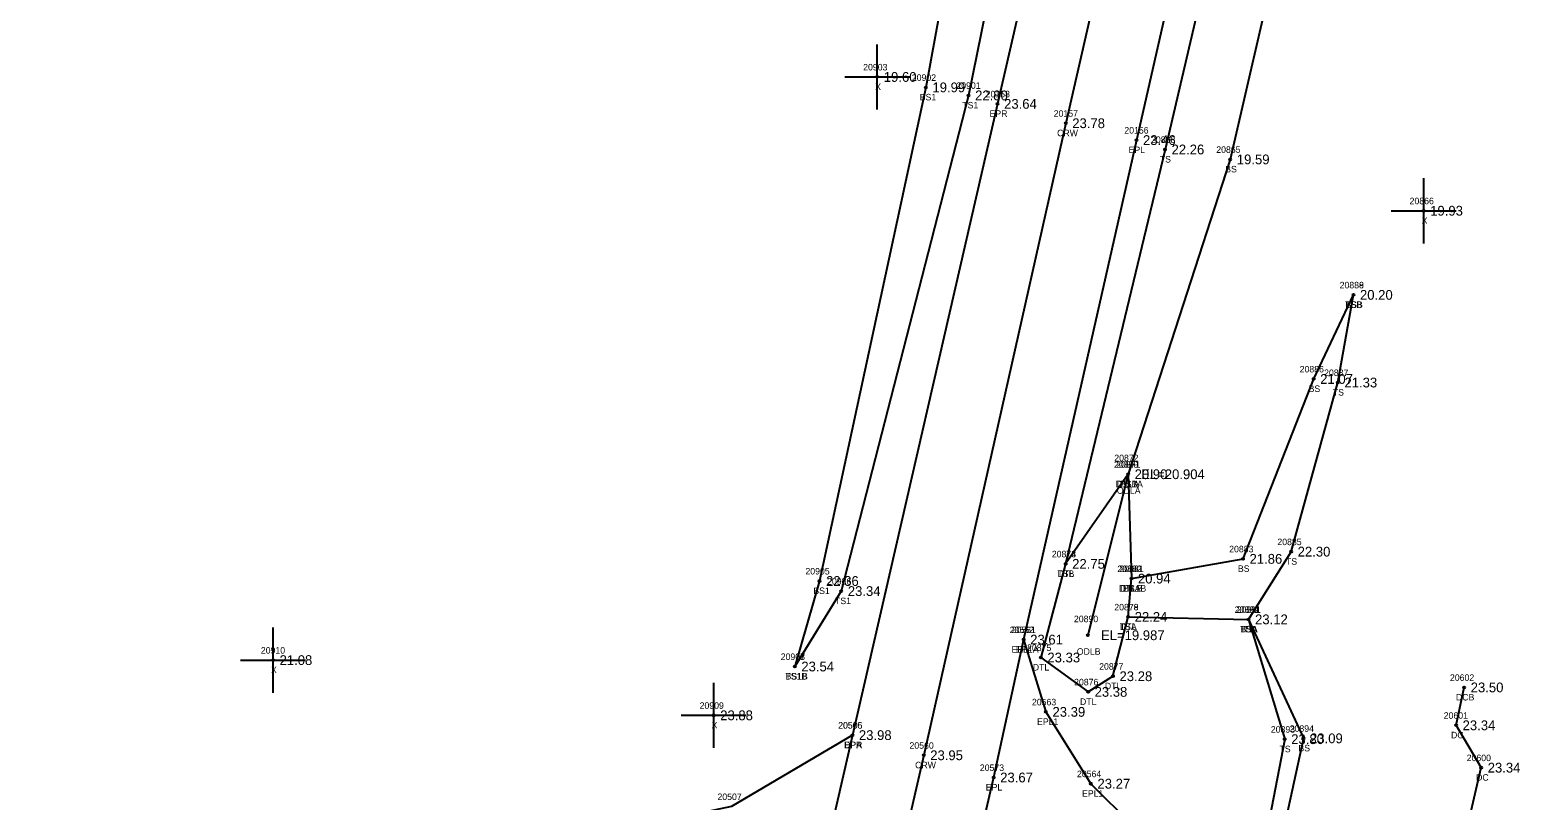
# Model space of a CAD drawing. Extents: x 2655177 to 2656219, y 761780 to 764748.
# Drawn here: x 2655478.9 to 2655710.1, y 762799.3 to 762917.5 of the extents above; entities that cross this region are included whole.
import ezdxf

# ---------------------------------------------------------------- set-up
doc = ezdxf.new("R2010")
doc.units = 0
for name, color, linetype in [('RD_DTM_BkLn1', 7, 'Continuous'), ('RD_DTM_BkLn2', 7, 'Continuous'), ('RD_DTM_BkLn_txCode', 7, 'Continuous'), ('RD_EX_Conc', 7, 'Continuous'), ('RD_EX_Conc_txCode', 7, 'Continuous'), ('RD_EX_Driveway', 7, 'Continuous'), ('RD_EX_Driveway_txCode', 7, 'Continuous'), ('RD_EX_H2O', 7, 'Continuous'), ('RD_EX_H2O_txCode', 7, 'Continuous'), ('RD_EX_Misc', 7, 'Continuous'), ('RD_EX_Misc_txCode', 7, 'Continuous'), ('RD_EX_Road', 7, 'Continuous'), ('RD_EX_Road_txCode', 7, 'Continuous'), ('RD_EX_TX_Conc_ELEV', 7, 'Continuous'), ('RD_EX_TX_Driveway_ELEV', 7, 'Continuous'), ('RD_EX_TX_H2O_ELEV', 7, 'Continuous'), ('RD_EX_TX_Misc_ELEV', 7, 'Continuous'), ('RD_EX_TX_Road_ELEV', 7, 'Continuous'), ('RD_HC_Survey_ELEV', 7, 'Continuous'), ('RD_HC_Survey_txCode', 7, 'Continuous'), ('RD_SMD_Locator', 7, 'Continuous')]:
    doc.layers.add(name, color=color, linetype=linetype)

msp = doc.modelspace()

# ---------------------------------------------------------------- linework, layer by layer
at = {"layer": 'RD_DTM_BkLn1'}
msp.add_lwpolyline([(2655711.06, 763230.3), (2655703.38, 763195.9), (2655681.97, 763099.65), (2655659.44, 762998.39), (2655637.72, 762903.26), (2655615.94, 762806.28), (2655593.94, 762710.45), (2655572.67, 762616.37), (2655551.12, 762519.58), (2655528.83, 762422.13), (2655507.58, 762326.81), (2655486.01, 762234.2), (2655464.77, 762141.12), (2655442.2, 762047.28), (2655420.99, 761952.95), (2655398.79, 761855.74), (2655384.11, 761791.21)], dxfattribs=at)
at = {"layer": 'RD_DTM_BkLn2'}
for points in [[(2655696.84, 763233.58), (2655686.81, 763240.78), (2655674.65, 763210.56), (2655653.92, 763107.89), (2655633.81, 763004.63), (2655616.28, 762908.76), (2655599.96, 762833.02), (2655596.17, 762819.9)], [(2655696.84, 763233.58), (2655686.68, 763198.57), (2655665.58, 763104.06), (2655642.01, 763002.21), (2655622.83, 762907.53), (2655603.3, 762831.47), (2655596.17, 762819.9)], [(2655744.66, 763205.12), (2655733.04, 763202.26), (2655726.56, 763191.09), (2655699.62, 763095.24), (2655675.04, 762993.86), (2655652.95, 762899.23), (2655637.71, 762835.65)], [(2655744.66, 763205.12), (2655742.37, 763185.6), (2655710.01, 763092), (2655684.24, 762990.11), (2655662.96, 762897.71), (2655647.29, 762849.4)], [(2655647.29, 762827.51), (2655665.76, 762827.13), (2655672.29, 762837.52), (2655679.47, 762863.47), (2655681.85, 762876.92)], [(2655647.79, 762833.39), (2655664.91, 762836.42), (2655675.75, 762864.02), (2655681.85, 762876.92)], [(2655665.76, 762827.13), (2655671.3, 762808.75), (2655668.39, 762793.68), (2655669.85, 762789.01)], [(2655665.76, 762827.13), (2655674.19, 762808.88), (2655670.96, 762794.12), (2655669.85, 762789.01)]]:
    msp.add_lwpolyline(points, dxfattribs=at)
at = {"layer": 'RD_EX_Conc'}
msp.add_lwpolyline([(2655695.58, 762778.92), (2655701.44, 762804.38), (2655697.59, 762810.88), (2655698.83, 762816.69)], dxfattribs=at)
at = {"layer": 'RD_EX_Driveway'}
msp.add_lwpolyline([(2655605, 762809.37), (2655586.47, 762798.41), (2655573.36, 762795.67), (2655559.24, 762787.47), (2655545.04, 762765.33), (2655541.01, 762760.72), (2655533.69, 762755.14), (2655505.04, 762752.17)], dxfattribs=at)
at = {"layer": 'RD_EX_H2O'}
for q in [(2655641.13, 762824.7), (2655647.79, 762833.39)]:
    msp.add_line((2655647.29, 762849.4), q, dxfattribs=at)
msp.add_lwpolyline([(2655647.29, 762849.4), (2655637.71, 762835.65), (2655633.91, 762821.28), (2655641.15, 762816.01), (2655644.97, 762818.41), (2655647.29, 762827.51), (2655647.79, 762833.39)], dxfattribs=at)
at = {"layer": 'RD_EX_Misc'}
for p, q in [((2655608.82, 762905.36), (2655608.82, 762915.36)), ((2655603.82, 762910.36), (2655613.82, 762910.36)), ((2655692.62, 762884.83), (2655692.62, 762894.83)), ((2655687.62, 762889.83), (2655697.62, 762889.83)), ((2655516.15, 762815.88), (2655516.15, 762825.88)), ((2655511.15, 762820.88), (2655521.15, 762820.88)), ((2655583.73, 762807.41), (2655583.73, 762817.41)), ((2655578.73, 762812.41), (2655588.73, 762812.41))]:
    msp.add_line(p, q, dxfattribs=at)
at = {"layer": 'RD_EX_Road'}
for points in [[(2655700.99, 763232.28), (2655693.55, 763198.57), (2655671.65, 763102.04), (2655649.04, 763001.06), (2655627.27, 762906.23), (2655605, 762809.37), (2655598.99, 762783.09), (2655583.65, 762714.14), (2655561.97, 762618.32), (2655556.36, 762593.84), (2655548.11, 762557.14), (2655540.1, 762522.48), (2655518.03, 762425.04), (2655496.48, 762329.56), (2655475.55, 762236.62), (2655473.2, 762226.14), (2655466.57, 762197.5), (2655460.06, 762168.16), (2655454.26, 762143.78), (2655432.5, 762049.88), (2655410.7, 761955.51), (2655388.17, 761858.43), (2655373.5, 761793.95)], [(2655722.66, 763227.87), (2655714.47, 763193.23), (2655692.89, 763097.26), (2655670.04, 762995.18), (2655648.57, 762900.67), (2655631.27, 762824.03), (2655626.67, 762802.87), (2655621.78, 762781.91), (2655611.71, 762738.43), (2655604.93, 762708.62), (2655582.64, 762610.54), (2655576.46, 762583.32), (2655561.41, 762517.24)], [(2655631.27, 762824.03), (2655634.69, 762812.94), (2655641.59, 762801.92), (2655647.95, 762795.55)]]:
    msp.add_lwpolyline(points, dxfattribs=at)
at = {"layer": 'RD_SMD_Locator'}
for centre in [(2655608.82, 762910.36), (2655616.28, 762908.76), (2655622.83, 762907.53), (2655627.27, 762906.23), (2655637.72, 762903.26), (2655648.57, 762900.67), (2655652.95, 762899.23), (2655662.96, 762897.71), (2655692.62, 762889.83), (2655681.85, 762876.92), (2655681.85, 762876.92), (2655675.75, 762864.02), (2655679.47, 762863.47), (2655647.29, 762849.4), (2655647.29, 762849.4), (2655647.29, 762849.4), (2655647.29, 762849.4), (2655672.29, 762837.52), (2655637.71, 762835.65), (2655637.71, 762835.65), (2655664.91, 762836.42), (2655599.96, 762833.02), (2655647.79, 762833.39), (2655647.79, 762833.39), (2655647.79, 762833.39), (2655603.3, 762831.47), (2655647.29, 762827.51), (2655647.29, 762827.51), (2655665.76, 762827.13), (2655665.76, 762827.13), (2655665.76, 762827.13), (2655631.27, 762824.03), (2655631.27, 762824.03), (2655641.13, 762824.7), (2655516.15, 762820.88), (2655633.91, 762821.28), (2655596.17, 762819.9), (2655596.17, 762819.9), (2655644.97, 762818.41), (2655698.83, 762816.69), (2655641.15, 762816.01), (2655583.73, 762812.41), (2655634.69, 762812.94), (2655605, 762809.37), (2655605, 762809.37), (2655697.59, 762810.88), (2655671.3, 762808.75), (2655674.19, 762808.88), (2655615.94, 762806.28), (2655626.67, 762802.87), (2655701.44, 762804.38), (2655641.59, 762801.92)]:
    msp.add_circle(centre, 0.15, dxfattribs=at)

# ---------------------------------------------------------------- texts
at = {"layer": 'RD_DTM_BkLn_txCode'}
for s, p in [('20902', (2655614.12, 762909.76)), ('20901', (2655620.95, 762908.53)), ('BS1', (2655615.33, 762906.76)), ('TS1', (2655621.86, 762905.53)), ('20868', (2655650.81, 762900.23)), ('20865', (2655660.81, 762898.71)), ('TS', (2655652.15, 762897.23)), ('BS', (2655662.18, 762895.71)), ('20888', (2655679.73, 762877.92)), ('20889', (2655679.73, 762877.92)), ('TSB', (2655680.58, 762874.92)), ('BSB', (2655680.6, 762874.92)), ('20886', (2655673.6, 762865.02)), ('20887', (2655677.35, 762864.47)), ('BS', (2655674.97, 762862.02)), ('TS', (2655678.68, 762861.47)), ('20869', (2655645.15, 762850.4)), ('BSB', (2655646.04, 762847.4)), ('20885', (2655670.18, 762838.52)), ('20873', (2655635.59, 762836.65)), ('20883', (2655662.79, 762837.42)), ('20905', (2655597.8, 762834.02)), ('20880', (2655645.63, 762834.39)), ('BS', (2655664.13, 762834.42)), ('TS', (2655671.5, 762835.52)), ('20906', (2655601.12, 762832.47)), ('TSB', (2655636.44, 762833.65)), ('BS1', (2655599.01, 762831.02)), ('TS1', (2655602.34, 762829.47)), ('BSA', (2655646.52, 762831.39)), ('20879', (2655645.17, 762828.51)), ('20884', (2655663.64, 762828.13)), ('20892', (2655663.64, 762828.13)), ('20891', (2655663.92, 762828.13)), ('TSA', (2655646.01, 762825.51)), ('TSA', (2655664.47, 762825.13)), ('BSA', (2655664.49, 762825.13)), ('TS', (2655664.96, 762825.13)), ('20907', (2655594.01, 762820.9)), ('20908', (2655594.01, 762820.9)), ('TS1B', (2655594.73, 762817.9)), ('BS1B', (2655594.75, 762817.9)), ('20893', (2655669.18, 762809.75)), ('20894', (2655672.07, 762809.88)), ('TS', (2655670.5, 762806.75)), ('BS', (2655673.41, 762806.88))]:
    msp.add_text(s, height=1, dxfattribs=at).set_placement(p)
at = {"layer": 'RD_EX_Conc_txCode'}
for s, p in [('20602', (2655696.65, 762817.69)), ('DCB', (2655697.57, 762814.69)), ('20601', (2655695.69, 762811.88)), ('DC', (2655696.81, 762808.88)), ('20600', (2655699.22, 762805.38)), ('DC', (2655700.66, 762802.38))]:
    msp.add_text(s, height=1, dxfattribs=at).set_placement(p)
at = {"layer": 'RD_EX_Driveway_txCode'}
for s, p in [('20506', (2655602.81, 762810.37)), ('DPA', (2655603.73, 762807.37)), ('20507', (2655584.31, 762799.41))]:
    msp.add_text(s, height=1, dxfattribs=at).set_placement(p)
at = {"layer": 'RD_EX_H2O_txCode'}
for s, p in [('20870', (2655645.13, 762850.4)), ('20872', (2655645.17, 762851.4)), ('20871', (2655645.45, 762850.4)), ('DTL1A', (2655645.39, 762847.4)), ('ODLA', (2655645.56, 762846.4)), ('DTLA', (2655645.56, 762847.4)), ('20874', (2655635.59, 762836.65)), ('20882', (2655645.67, 762834.39)), ('20881', (2655645.96, 762834.39)), ('DTL', (2655636.46, 762833.65)), ('DTL1B', (2655645.91, 762831.39)), ('DTLB', (2655646.08, 762831.39)), ('20878', (2655645.17, 762828.51)), ('20890', (2655638.98, 762826.7)), ('DTL', (2655646.05, 762825.51)), ('20875', (2655631.79, 762822.28)), ('ODLB', (2655639.42, 762821.7)), ('DTL', (2655632.67, 762819.28)), ('20877', (2655642.85, 762819.41)), ('20876', (2655639.01, 762817.01)), ('DTL', (2655643.72, 762816.41)), ('DTL', (2655639.91, 762814.01))]:
    msp.add_text(s, height=1, dxfattribs=at).set_placement(p)
at = {"layer": 'RD_EX_Misc_txCode'}
for s, p in [('20903', (2655606.66, 762911.36)), ('X', (2655608.5, 762908.36)), ('20866', (2655690.46, 762890.83)), ('X', (2655692.31, 762887.83)), ('20910', (2655514.28, 762821.88)), ('X', (2655515.84, 762818.88)), ('20909', (2655581.57, 762813.41)), ('X', (2655583.41, 762810.41))]:
    msp.add_text(s, height=1, dxfattribs=at).set_placement(p)
at = {"layer": 'RD_EX_Road_txCode'}
for s, p in [('20158', (2655625.44, 762907.23)), ('EPR', (2655626.04, 762904.23)), ('20156', (2655646.71, 762901.67)), ('EPL', (2655647.36, 762898.67)), ('20562', (2655629.13, 762825.03)), ('20561', (2655629.41, 762825.03)), ('EPL1A', (2655629.41, 762822.03)), ('EPL', (2655630.07, 762822.03)), ('20563', (2655632.54, 762813.94)), ('EPL1', (2655633.32, 762810.94)), ('20505', (2655602.84, 762810.37)), ('EPR', (2655603.77, 762807.37)), ('20573', (2655624.55, 762803.87)), ('20564', (2655639.45, 762802.92)), ('EPL', (2655625.46, 762800.87)), ('EPL1', (2655640.22, 762799.92))]:
    msp.add_text(s, height=1, dxfattribs=at).set_placement(p)
at = {"layer": 'RD_EX_TX_Conc_ELEV'}
for s, p in [('23.50', (2655699.83, 762815.94)), ('23.34', (2655698.59, 762810.13)), ('23.34', (2655702.44, 762803.63))]:
    msp.add_text(s, height=1.5, dxfattribs=at).set_placement(p)
at = {"layer": 'RD_EX_TX_Driveway_ELEV'}
msp.add_text('23.98', height=1.5, dxfattribs=at).set_placement((2655606, 762808.62))
at = {"layer": 'RD_EX_TX_H2O_ELEV'}
for s, p in [('20.90', (2655648.29, 762848.65)), ('20.90', (2655648.29, 762848.65)), ('EL=20.904', (2655649.29, 762848.65)), ('22.75', (2655638.71, 762834.9)), ('20.94', (2655648.79, 762832.64)), ('20.94', (2655648.79, 762832.64)), ('22.24', (2655648.29, 762826.76)), ('EL=19.987', (2655643.13, 762823.95)), ('23.33', (2655634.91, 762820.53)), ('23.28', (2655645.97, 762817.66)), ('23.38', (2655642.15, 762815.26))]:
    msp.add_text(s, height=1.5, dxfattribs=at).set_placement(p)
at = {"layer": 'RD_EX_TX_Misc_ELEV'}
for s, p in [('19.60', (2655609.82, 762909.61)), ('19.99', (2655617.28, 762908.01)), ('22.80', (2655623.83, 762906.78)), ('22.26', (2655653.95, 762898.48)), ('19.59', (2655663.96, 762896.96)), ('19.93', (2655693.62, 762889.08)), ('20.20', (2655682.85, 762876.17)), ('20.20', (2655682.85, 762876.17)), ('21.07', (2655676.75, 762863.27)), ('21.33', (2655680.47, 762862.72)), ('20.90', (2655648.29, 762848.65)), ('21.86', (2655665.91, 762835.67)), ('22.30', (2655673.29, 762836.77)), ('22.75', (2655638.71, 762834.9)), ('22.36', (2655600.96, 762832.27)), ('20.94', (2655648.79, 762832.64)), ('23.34', (2655604.3, 762830.72)), ('22.24', (2655648.29, 762826.76)), ('23.12', (2655666.76, 762826.38)), ('23.12', (2655666.76, 762826.38)), ('23.12', (2655666.76, 762826.38)), ('21.08', (2655517.15, 762820.13)), ('23.54', (2655597.17, 762819.15)), ('23.54', (2655597.17, 762819.15)), ('23.88', (2655584.73, 762811.66)), ('23.80', (2655672.3, 762808)), ('23.09', (2655675.19, 762808.13))]:
    msp.add_text(s, height=1.5, dxfattribs=at).set_placement(p)
at = {"layer": 'RD_EX_TX_Road_ELEV'}
for s, p in [('23.64', (2655628.27, 762905.48)), ('23.46', (2655649.57, 762899.92)), ('23.61', (2655632.27, 762823.28)), ('23.61', (2655632.27, 762823.28)), ('23.39', (2655635.69, 762812.19)), ('23.98', (2655606, 762808.62)), ('23.67', (2655627.67, 762802.12)), ('23.27', (2655642.59, 762801.17))]:
    msp.add_text(s, height=1.5, dxfattribs=at).set_placement(p)
at = {"layer": 'RD_HC_Survey_ELEV'}
for s, p in [('23.78', (2655638.72, 762902.51)), ('23.95', (2655616.94, 762805.53))]:
    msp.add_text(s, height=1.5, dxfattribs=at).set_placement(p)
at = {"layer": 'RD_HC_Survey_txCode'}
for s, p in [('20157', (2655635.88, 762904.26)), ('CRW', (2655636.4, 762901.26)), ('20560', (2655613.76, 762807.28)), ('CRW', (2655614.62, 762804.28))]:
    msp.add_text(s, height=1, dxfattribs=at).set_placement(p)

doc.saveas('drawing.dxf')
